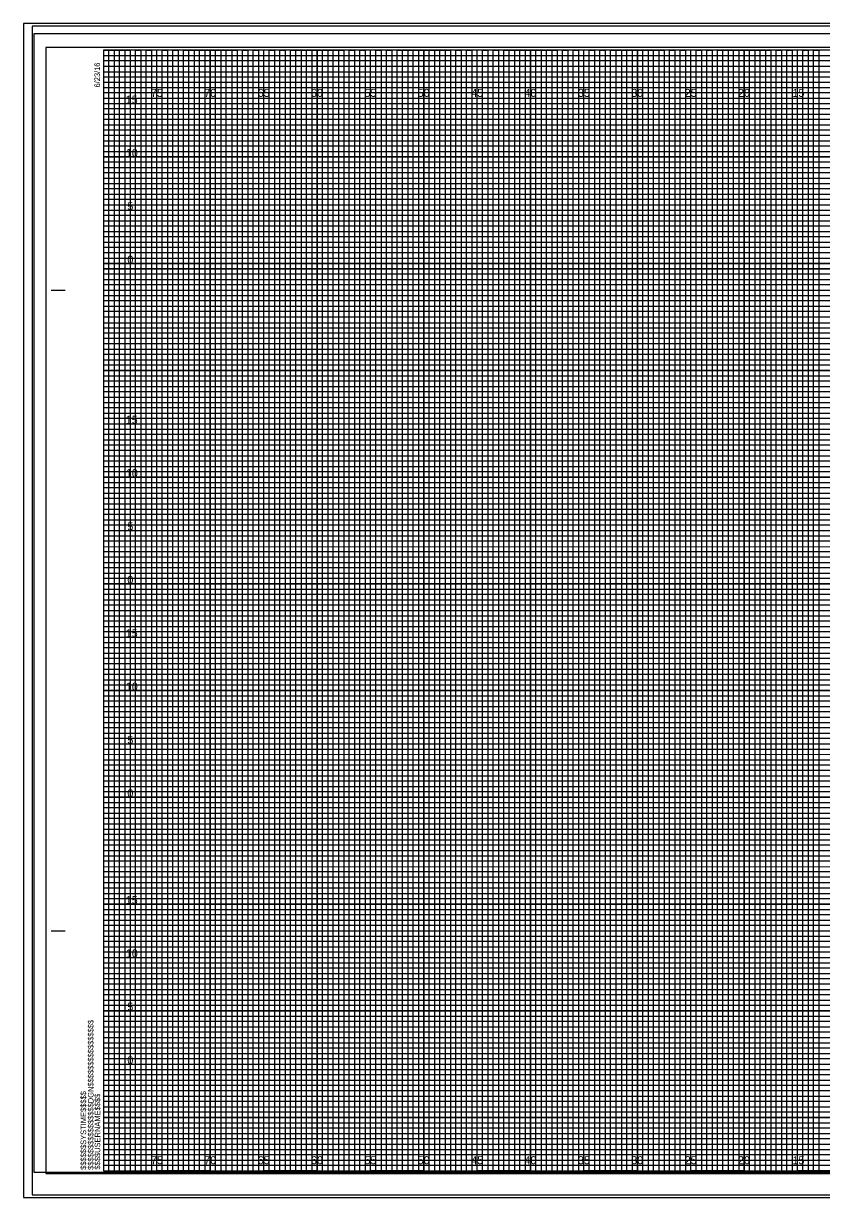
# Model space of a CAD drawing. Extents: x -8 to 162, y 108 to 218.
import ezdxf

# ---------------------------------------------------------------- set-up
doc = ezdxf.new("R2010")
doc.units = 0
for name, color, linetype in [('Prop XS Elevation Labels', 7, 'Continuous'), ('Prop XS Offset Labels', 7, 'Continuous'), ('Sheet Cross Section CELL', 7, 'Continuous'), ('Sheet Cross Section Grid Major CELL', 7, 'Continuous'), ('Sheet Cross Section Grid Middle CELL', 7, 'Continuous'), ('Sheet Cross Section Grid Minor 1 CELL', 7, 'Continuous'), ('Sheet Cross Section Grid Minor 2 CELL', 7, 'Continuous'), ('Sheet Cutting Line CELL', 7, 'Continuous'), ('Sheet DOT Grid CELL', 7, 'Continuous'), ('Sheet Plot Border Inside CELL', 7, 'Continuous'), ('Sheet Plot Border Outside CELL', 7, 'Continuous'), ('Stewart Plot Border DJ1055', 7, 'Continuous'), ('Stewart Plot Border DJ1055 Invisible', 7, 'Continuous'), ('Stewart Plot Border Xerox6279 and LJ5000', 7, 'Continuous')]:
    doc.layers.add(name, color=color, linetype=linetype)

msp = doc.modelspace()

# ---------------------------------------------------------------- linework, layer by layer
at = {"layer": 'Sheet Cross Section CELL'}
for p, q in [((-4.9, 192.5), (-3.65, 192.5)), ((-4.85, 192.5), (-3.6, 192.5)), ((-4.9, 132.5), (-3.65, 132.5)), ((-4.85, 132.5), (-3.6, 132.5)), ((0, 110), (0, 110)), ((0, 110), (0, 110)), ((0, 110), (0, 110)), ((0, 110), (0, 110)), ((0, 110), (0, 110)), ((0, 110), (0, 110)), ((0, 110), (0, 110))]:
    msp.add_line(p, q, dxfattribs=at)
msp.add_lwpolyline([(160, 215), (0, 215), (0, 110), (160, 110)], close=True, dxfattribs=at)
at = {"layer": 'Sheet Cross Section Grid Major CELL'}
for p, q in [((5, 215), (0, 215)), ((5, 110), (5, 215)), ((15, 215), (10, 215)), ((10, 215), (10, 110)), ((15, 110), (15, 215)), ((25, 215), (20, 215)), ((20, 215), (20, 110)), ((25, 110), (25, 215)), ((35, 215), (30, 215)), ((30, 215), (30, 110)), ((35, 110), (35, 215)), ((45, 215), (40, 215)), ((40, 215), (40, 110)), ((45, 110), (45, 215)), ((55, 215), (50, 215)), ((50, 215), (50, 110)), ((55, 110), (55, 215)), ((65, 215), (60, 215)), ((60, 215), (60, 110)), ((65, 110), (65, 215)), ((10, 110), (5, 110)), ((20, 110), (15, 110)), ((30, 110), (25, 110)), ((40, 110), (35, 110)), ((50, 110), (45, 110)), ((60, 110), (55, 110)), ((70, 110), (65, 110))]:
    msp.add_line(p, q, dxfattribs=at)
for points in [[(0, 210), (160, 210), (160, 205), (0, 205)], [(0, 200), (160, 200), (160, 195), (0, 195)], [(0, 190), (160, 190), (160, 185), (0, 185)], [(0, 180), (160, 180), (160, 175), (0, 175)], [(0, 170), (160, 170), (160, 165), (0, 165)], [(0, 160), (160, 160), (160, 155), (0, 155)], [(0, 150), (160, 150), (160, 145), (0, 145)], [(0, 140), (160, 140), (160, 135), (0, 135)], [(0, 130), (160, 130), (160, 125), (0, 125)], [(0, 120), (160, 120), (160, 115), (0, 115)]]:
    msp.add_lwpolyline(points, dxfattribs=at)
at = {"layer": 'Sheet Cross Section Grid Middle CELL'}
for points in [[(0, 215), (2.5, 215), (2.5, 110), (7.5, 110), (7.5, 215), (12.5, 215), (12.5, 110), (17.5, 110), (17.5, 215), (22.5, 215), (22.5, 110), (27.5, 110), (27.5, 215), (32.5, 215), (32.5, 110), (37.5, 110), (37.5, 215), (42.5, 215), (42.5, 110), (47.5, 110), (47.5, 215), (52.5, 215), (52.5, 110), (57.5, 110), (57.5, 215), (62.5, 215), (62.5, 110), (67.5, 110)], [(0, 212.5), (137.5, 212.5)], [(0, 202.5), (160, 202.5), (160, 207.5), (0, 207.5)], [(0, 192.5), (160, 192.5), (160, 197.5), (0, 197.5)], [(0, 182.5), (160, 182.5), (160, 187.5), (0, 187.5)], [(0, 172.5), (160, 172.5), (160, 177.5), (0, 177.5)], [(0, 162.5), (160, 162.5), (160, 167.5), (0, 167.5)], [(0, 152.5), (160, 152.5), (160, 157.5), (0, 157.5)], [(0, 142.5), (160, 142.5), (160, 147.5), (0, 147.5)], [(0, 132.5), (160, 132.5), (160, 137.5), (0, 137.5)], [(0, 122.5), (160, 122.5), (160, 127.5), (0, 127.5)], [(0, 112.5), (160, 112.5), (160, 117.5), (0, 117.5)]]:
    msp.add_lwpolyline(points, dxfattribs=at)
at = {"layer": 'Sheet Cross Section Grid Minor 1 CELL'}
for p, q in [((0, 214.5), (130, 214.5)), ((130, 213.99), (0, 213.99)), ((0, 213.99), (0, 213.5)), ((0, 213.5), (130, 213.5)), ((130, 212.94), (0, 212.94)), ((0, 212.94), (0, 212)), ((0, 212), (160, 212))]:
    msp.add_line(p, q, dxfattribs=at)
for points in [[(0, 211.5), (135, 211.5), (160, 211.5), (160, 211), (0, 211)], [(0, 210.5), (160, 210.5), (160, 209.5), (0, 209.5)], [(0, 209), (160, 209), (160, 208.5), (0, 208.49)], [(0, 208), (160, 208), (160, 207), (0, 207)], [(0, 206.5), (160, 206.5), (160, 206), (0, 206)], [(0, 205.5), (160, 205.5), (160, 204.5), (0, 204.5)], [(0, 204), (160, 204), (160, 203.5), (0, 203.5)], [(0, 203), (160, 203), (160, 202), (0, 202)], [(0, 201.5), (160, 201.5), (160, 201), (0, 201)], [(0, 200.5), (160, 200.5), (160, 199.5), (0, 199.5)], [(0, 199), (160, 199), (160, 198.5), (0, 198.5)], [(0, 198), (160, 198), (160, 196.97), (160, 196.5), (160, 196), (0, 196)], [(0, 197), (160, 197), (160, 196.5), (0, 196.5)], [(0, 195.5), (160, 195.5), (160, 194.5), (0, 194.52)], [(0, 194.52), (160, 194.5), (160, 194), (0, 194)], [(0, 193.5), (160, 193.5), (160, 193), (0, 193)], [(0, 192), (160, 192), (160, 191.5), (0, 191.5)], [(0, 191), (160, 191), (160, 190.5), (0, 190.5)], [(-0.04, 189.44), (160, 189.44), (160, 188.94), (-0.04, 188.94)], [(0, 188.5), (160, 188.5), (160, 188), (0, 188)], [(0, 187), (160, 187), (160, 186.5), (0, 186.5)], [(0, 186), (160, 186), (160, 185.5), (0, 185.5)], [(0, 184.5), (160, 184.5), (160, 184), (0, 184)], [(0, 183.5), (160, 183.5), (160, 183), (0, 183)], [(0, 182), (160, 182), (160, 181.5), (0, 181.5)], [(0, 181), (160, 181), (160, 180.5), (0, 180.5)], [(0, 179.5), (160, 179.5), (160, 178.99), (0, 179)], [(0, 178.5), (160, 178.5), (160, 178), (0, 178)], [(0, 177), (160, 177), (160, 176.5), (0, 176.5)], [(0, 176), (160, 176), (160, 175.5), (0, 175.5)], [(0, 174.5), (160, 174.5), (160, 174), (0, 174)], [(0, 173.5), (160, 173.5), (160, 173), (0, 173)], [(0, 172), (160, 172), (160, 171.5), (0, 171.5)], [(0, 171), (160, 171), (160, 170.5), (0, 170.5)], [(0, 169.5), (160, 169.5), (160, 169), (0, 169)], [(0, 168.5), (160.03, 168.46), (160, 168), (0, 168)], [(0, 167), (160, 167), (160, 166.5), (0, 166.5)], [(0, 166), (160, 166), (160, 165.5), (0, 165.5)], [(0, 164.5), (160, 164.5), (160, 164), (0, 164)], [(0, 163.5), (160, 163.5), (160, 163), (0, 163)], [(0, 162), (160, 162), (160, 161.5), (0, 161.5)], [(0, 161), (160, 161), (160, 160.5), (0, 160.5)], [(0, 159.5), (160, 159.5), (160, 159), (0, 159)], [(0, 158.5), (160, 158.5), (160, 158), (0, 158)], [(0, 157), (160, 157), (160, 156.5), (0, 156.5)], [(0, 156), (160, 156), (160, 155.5), (0, 155.5)], [(0, 154.5), (160, 154.5), (160, 154), (0, 154)], [(0, 153.5), (160, 153.5), (160, 153), (0, 153)], [(0, 152), (160, 152), (160, 151.5), (0, 151.5)], [(0, 151), (160, 151), (160, 150.5), (0, 150.5)], [(0, 149.5), (160, 149.5), (160, 148.99), (0, 149)], [(0, 148.5), (160, 148.5), (160, 148), (0, 148)], [(0, 147), (160, 147), (160, 146.5), (0, 146.5)], [(0, 146), (160, 146), (160, 145.5), (0, 145.5)], [(0, 144.5), (160, 144.5), (160, 144), (0, 144)], [(0, 143.5), (160, 143.5), (160, 143), (0, 143)], [(0, 142), (160, 142), (160, 141.5), (0, 141.5)], [(0, 141), (160, 141), (160, 140.5), (0, 140.5)], [(0, 139.5), (160, 139.5), (160, 139), (0, 139)], [(0, 138.5), (160.03, 138.46), (160, 138), (0, 138)], [(0, 137), (160, 137), (160, 136.5), (0, 136.5)], [(0, 136), (160, 136), (160, 135.5), (0, 135.5)], [(0, 134.5), (160, 134.5), (160, 134), (0, 134)], [(0, 133.5), (160, 133.5), (160, 133), (0, 133)], [(0, 132), (160, 132), (160, 131.5), (0, 131.5)], [(0, 131), (160, 131), (160, 130.5), (0, 130.5)], [(0, 129.5), (160, 129.5), (160, 129), (0, 129)], [(0, 128.5), (160, 128.5), (160, 128), (0, 128)], [(0, 127), (160, 127), (160, 126.5), (0, 126.5)], [(0, 126), (160, 126), (160, 125.5), (0, 125.5)], [(0, 124.5), (160, 124.5), (160, 124), (0, 124)], [(0, 123.5), (160, 123.5), (160, 123), (0, 123)], [(0, 122), (160, 122), (160, 121.5), (0, 121.5)], [(0, 121), (160, 121), (160, 120.5), (0, 120.5)], [(0, 119.5), (160, 119.5), (160, 119), (0, 119)], [(0, 118.5), (160, 118.5), (160, 118), (0, 118)], [(0, 117), (160, 117), (160, 116.5), (0, 116.5)], [(0, 116), (160, 116), (160, 115.5), (0, 115.5)], [(0, 114.5), (160, 114.5), (160, 114), (0, 114)], [(0, 113.5), (160, 113.5), (160, 113), (0, 113)], [(0, 112), (160, 112), (160, 111.5), (0, 111.5)], [(0, 111), (160, 111), (160, 110.5), (0, 110.5)]]:
    msp.add_lwpolyline(points, dxfattribs=at)
at = {"layer": 'Sheet Cross Section Grid Minor 2 CELL'}
for points in [[(0, 110), (0.5, 110), (0.5, 215), (1, 215), (1, 110)], [(1, 110), (1.5, 110), (1.5, 215), (2, 215), (2, 110)], [(2.5, 110), (3, 110), (3, 215), (3.5, 215), (3.5, 110)], [(3.5, 110), (4, 110), (4, 215), (4.5, 215), (4.5, 110)], [(5, 110), (5.5, 110), (5.5, 215), (6, 215), (6, 110)], [(6, 110), (6.5, 110), (6.5, 215), (7, 215), (7, 110)], [(7.5, 110), (8, 110), (8, 215), (8.5, 215), (8.5, 110)], [(8.5, 110), (9, 110), (9, 215), (9.5, 215), (9.5, 110)], [(10, 110), (10.5, 110), (10.5, 215), (11, 215), (11, 110)], [(11, 110), (11.5, 110), (11.5, 215), (12, 215), (12, 110)], [(12.5, 110), (13, 110), (13, 215), (13.5, 215), (13.5, 110)], [(13.5, 110), (14, 110), (14, 215), (14.5, 215), (14.5, 110)], [(15, 110), (15.5, 110), (15.5, 215), (16, 215), (16, 110)], [(16, 110), (16.5, 110), (16.5, 215), (17, 215), (17, 110)], [(17.5, 110), (18, 110), (18, 215), (18.5, 215), (18.5, 110)], [(18.5, 110), (19, 110), (19, 215), (19.5, 215), (19.5, 110)], [(20, 110), (20.5, 110), (20.5, 215), (21, 215), (21, 110)], [(21, 110), (21.5, 110), (21.5, 215), (22, 215), (22, 110)], [(22.5, 110), (23, 110), (23, 215), (23.5, 215), (23.5, 110)], [(23.5, 110), (24, 110), (24, 215), (24.5, 215), (24.5, 110)], [(25, 110), (25.5, 110), (25.5, 215), (26, 215), (26, 110)], [(26, 110), (26.5, 110), (26.5, 215), (27, 215), (27, 110)], [(27.5, 110), (28, 110), (28, 215), (28.5, 215), (28.5, 110)], [(28.5, 110), (29, 110), (29, 215), (29.5, 215), (29.5, 110)], [(30, 110), (30.5, 110), (30.5, 215), (31, 215), (31, 110)], [(31, 110), (31.5, 110), (31.5, 215), (32, 215), (32, 110)], [(32.5, 110), (33, 110), (33, 215), (33.5, 215), (33.5, 110)], [(33.5, 110), (34, 110), (34, 215), (34.5, 215), (34.5, 110)], [(35, 110), (35.5, 110), (35.5, 215), (36, 215), (36, 110)], [(36, 110), (36.5, 110), (36.5, 215), (37, 215), (37, 110)], [(37.5, 110), (38, 110), (38, 215), (38.5, 215), (38.5, 110)], [(38.5, 110), (39, 110), (39, 215), (39.5, 215), (39.5, 110)], [(40, 110), (40.5, 110), (40.5, 215), (41, 215), (41, 110)], [(41, 110), (41.5, 110), (41.5, 215), (42, 215), (42, 110)], [(42.5, 110), (43, 110), (43, 215), (43.5, 215), (43.5, 110)], [(43.5, 110), (44, 110), (44, 215), (44.5, 215), (44.5, 110)], [(45, 110), (45.5, 110), (45.5, 215), (46, 215), (46, 110)], [(46, 110), (46.5, 110), (46.5, 215), (47, 215), (47, 110)], [(47.5, 110), (48, 110), (48, 215), (48.5, 215), (48.5, 110)], [(48.5, 110), (49, 110), (49, 215), (49.5, 215), (49.5, 110)], [(50, 110), (50.5, 110), (50.5, 215), (51, 215), (51, 110)], [(51, 110), (51.5, 110), (51.5, 215), (52, 215), (52, 110)], [(52.5, 110), (53, 110), (53, 215), (53.5, 215), (53.5, 110)], [(53.5, 110), (54, 110), (54, 215), (54.5, 215), (54.5, 110)], [(55, 110), (55.5, 110), (55.5, 215), (56, 215), (56, 110)], [(56, 110), (56.5, 110), (56.5, 215), (57, 215), (57, 110)], [(57.5, 110), (58, 110), (58, 215), (58.5, 215), (58.5, 110)], [(58.5, 110), (59, 110), (59, 215), (59.5, 215), (59.5, 110)], [(60, 110), (60.5, 110), (60.5, 215), (61, 215), (61, 110)], [(61, 110), (61.5, 110), (61.5, 215), (62, 215), (62, 110)], [(62.5, 110), (63, 110), (63, 215), (63.5, 215), (63.5, 110)], [(63.5, 110), (64, 110), (64, 215), (64.5, 215), (64.5, 110)], [(65, 110), (65.5, 110), (65.5, 215), (66, 215), (66, 110)], [(66, 110), (66.5, 110), (66.5, 215), (67, 215), (67, 110)]]:
    msp.add_lwpolyline(points, dxfattribs=at)
at = {"layer": 'Sheet Cutting Line CELL'}
for p, q in [((161.65, 217.25), (-6.7, 217.25)), ((-6.7, 217.25), (-6.7, 107.75)), ((-6.7, 107.75), (161.65, 107.75))]:
    msp.add_line(p, q, dxfattribs=at)
at = {"layer": 'Sheet DOT Grid CELL'}
for p, q in [((5, 110), (5, 215)), ((10, 110), (10, 215)), ((15, 110), (15, 215)), ((20, 110), (20, 215)), ((25, 110), (25, 215)), ((30, 110), (30, 215)), ((35, 110), (35, 215)), ((40, 110), (40, 215)), ((45, 110), (45, 215)), ((50, 110), (50, 215)), ((55, 110), (55, 215)), ((60, 110), (60, 215)), ((65, 110), (65, 215)), ((0, 210), (160, 210)), ((0, 205), (160, 205)), ((0, 200), (160, 200)), ((0, 195), (160, 195)), ((0, 190), (160, 190)), ((0, 185), (160, 185)), ((0, 180), (160, 180)), ((0, 175), (160, 175)), ((0, 170), (160, 170)), ((0, 165), (160, 165)), ((0, 160), (160, 160)), ((0, 155), (160, 155)), ((0, 150), (160, 150)), ((0, 145), (160, 145)), ((0, 140), (160, 140)), ((0, 135), (160, 135)), ((0, 130), (160, 130)), ((0, 125), (160, 125)), ((0, 120), (160, 120)), ((0, 115), (160, 115))]:
    msp.add_line(p, q, dxfattribs=at)
at = {"layer": 'Sheet Plot Border Inside CELL'}
msp.add_lwpolyline([(-5.4, 109.75), (161.2, 109.75), (161.2, 215.25), (-5.4, 215.25)], close=True, dxfattribs=at)
at = {"layer": 'Sheet Plot Border Outside CELL'}
msp.add_lwpolyline([(-6.7, 107.75), (161.65, 107.75), (161.65, 217.25), (-6.7, 217.25)], close=True, dxfattribs=at)
at = {"layer": 'Stewart Plot Border DJ1055'}
msp.add_lwpolyline([(161.52, 216.53), (-6.52, 216.53), (-6.52, 109.87), (161.52, 109.87)], close=True, dxfattribs=at)
at = {"layer": 'Stewart Plot Border DJ1055 Invisible'}
msp.add_lwpolyline([(161.52, 216.53), (-6.52, 216.53), (-6.52, 109.87), (161.52, 109.87)], close=True, dxfattribs=at)
at = {"layer": 'Stewart Plot Border Xerox6279 and LJ5000'}
msp.add_lwpolyline([(-7.5, 107.5), (162.5, 107.5), (162.5, 217.5), (-7.5, 217.5)], close=True, dxfattribs=at)

# ---------------------------------------------------------------- texts
at = {"layer": 'Prop XS Elevation Labels'}
for s, p in [('15', (2.08, 210)), ('10', (2.09, 205)), ('5', (2.23, 200)), ('0', (2.23, 195)), ('15', (2.08, 180)), ('10', (2.09, 175)), ('5', (2.23, 170)), ('0', (2.23, 165)), ('15', (2.08, 160)), ('10', (2.09, 155)), ('5', (2.23, 150)), ('0', (2.23, 145)), ('15', (2.08, 135)), ('10', (2.09, 130)), ('5', (2.23, 125)), ('0', (2.23, 120))]:
    msp.add_text(s, height=0.75, dxfattribs=at).set_placement(p)
at = {"layer": 'Prop XS Offset Labels'}
for s, p in [('75', (4.44, 210.62)), ('70', (9.43, 210.62)), ('65', (14.44, 210.62)), ('60', (19.43, 210.62)), ('55', (24.44, 210.62)), ('50', (29.43, 210.62)), ('45', (34.44, 210.62)), ('40', (39.43, 210.62)), ('35', (44.44, 210.62)), ('30', (49.43, 210.62)), ('25', (54.44, 210.62)), ('20', (59.43, 210.62)), ('15', (64.53, 210.62)), ('75', (4.44, 110.62)), ('70', (9.43, 110.62)), ('65', (14.44, 110.62)), ('60', (19.43, 110.62)), ('55', (24.44, 110.62)), ('50', (29.43, 110.62)), ('45', (34.44, 110.62)), ('40', (39.43, 110.62)), ('35', (44.44, 110.62)), ('30', (49.43, 110.62)), ('25', (54.44, 110.62)), ('20', (59.43, 110.62)), ('15', (64.53, 110.62))]:
    msp.add_text(s, height=0.75, dxfattribs=at).set_placement(p)
at = {"layer": 'Sheet Cross Section CELL'}
for s, p in [('6/23/16', (-0.33, 211.5)), ('$$$$$$$$$$$$$$$$DGN$$$$$$$$$$$$$$$$', (-0.94, 110.09)), ('$$$$$$SYSTIME$$$$$', (-1.63, 110.09)), ('$$$$USERNAME$$$$', (-0.31, 110.12))]:
    msp.add_text(s, height=0.525, rotation=90, dxfattribs=at).set_placement(p)

doc.saveas('drawing.dxf')
